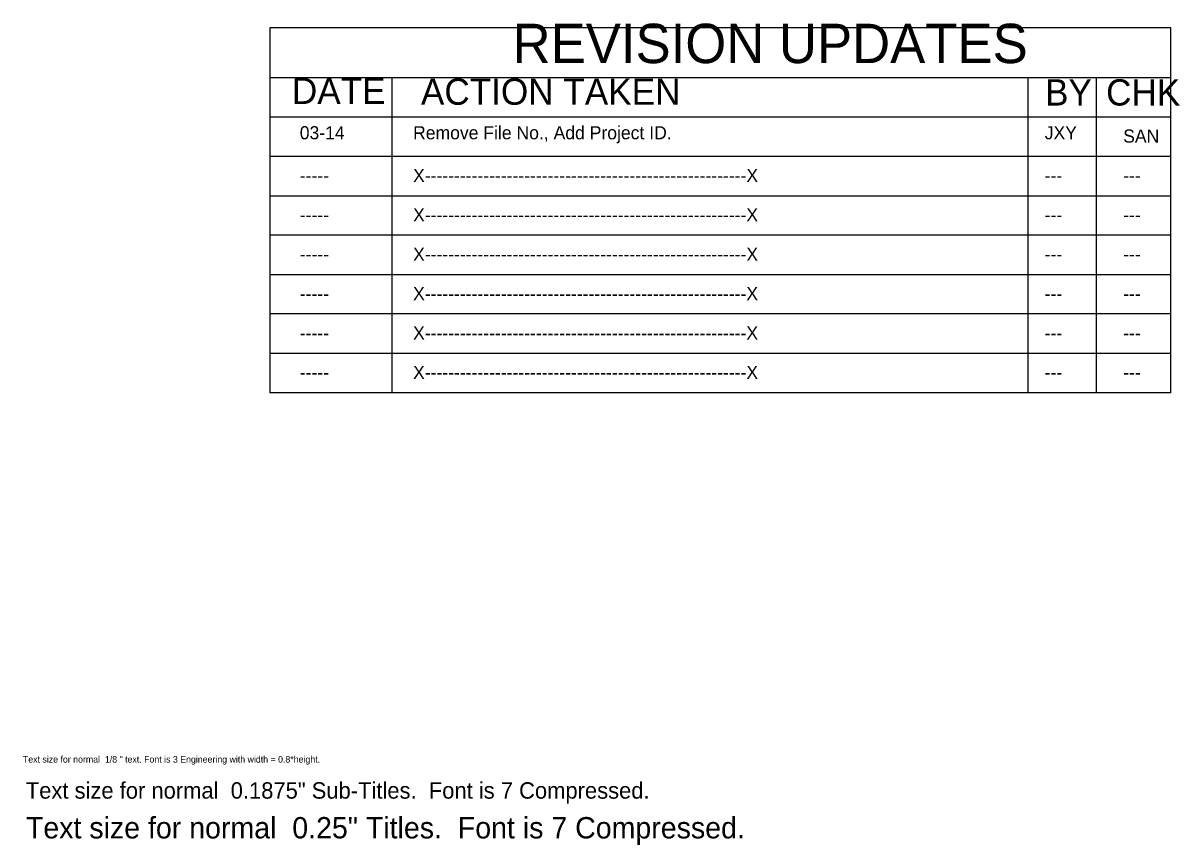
# Model space of a CAD drawing. Extents: x -0.04 to 4.87, y 0 to 1.83.
# Drawn here: x 3.035 to 4.87, y 0.217 to 1.521 of the extents above; entities that cross this region are included whole.
import ezdxf

# ---------------------------------------------------------------- set-up
doc = ezdxf.new("R2010")
doc.units = 0
doc.layers.add('BR_BORDER LINES', color=7, linetype='Continuous')
doc.layers.add('BR_TEXT', color=7, linetype='Continuous')

msp = doc.modelspace()

# ---------------------------------------------------------------- linework, layer by layer
at = {"layer": 'BR_BORDER LINES'}
for p, q in [((4.8558, 1.5135), (3.4261, 1.5135)), ((3.4261, 1.5135), (3.4261, 0.9345)), ((4.8558, 0.9345), (4.8558, 1.5135)), ((3.4261, 1.4346), (4.8558, 1.4346)), ((3.62, 1.4346), (3.62, 0.9345)), ((4.6296, 0.9345), (4.6296, 1.4346)), ((4.7373, 1.4346), (4.7373, 0.9345)), ((3.4261, 1.3721), (4.8558, 1.3721)), ((4.8558, 1.3095), (3.4261, 1.3095)), ((3.4261, 1.247), (4.8558, 1.247)), ((4.8558, 1.1845), (3.4261, 1.1845)), ((3.4261, 1.122), (4.8558, 1.122)), ((4.8558, 1.0595), (3.4261, 1.0595)), ((3.4261, 0.997), (4.8558, 0.997)), ((4.8558, 0.9345), (3.4261, 0.9345))]:
    msp.add_line(p, q, dxfattribs=at)

# ---------------------------------------------------------------- texts
at = {"layer": 'BR_TEXT'}
for s, height, p in [('REVISION UPDATES', 0.0625, (3.8114, 1.4575)), ('DATE', 0.04167, (3.4613, 1.3926)), ('ACTION TAKEN', 0.041667, (3.666, 1.3914)), ('BY', 0.04167, (4.6562, 1.3902)), ('CHK', 0.04167, (4.7531, 1.3902)), ('Remove File No., Add Project ID.                         ', 0.020833, (3.6535, 1.3366)), ('03-14', 0.02083, (3.4737, 1.3366)), ('JXY', 0.02083, (4.6557, 1.3366)), ('SAN', 0.02083, (4.7802, 1.3313)), ('X-------------------------------------------------------X', 0.020833, (3.6535, 1.2688)), ('-----', 0.02083, (3.4737, 1.2688)), ('---', 0.02083, (4.6557, 1.2688)), ('---', 0.02083, (4.7802, 1.2688)), ('-----', 0.02083, (3.4737, 1.2063)), ('X-------------------------------------------------------X', 0.020833, (3.6535, 1.2063)), ('---', 0.02083, (4.6557, 1.2063)), ('---', 0.02083, (4.7802, 1.2063)), ('X-------------------------------------------------------X', 0.020833, (3.6535, 1.1438)), ('-----', 0.02083, (3.4737, 1.1438)), ('---', 0.02083, (4.6557, 1.1438)), ('---', 0.02083, (4.7802, 1.1438)), ('X-------------------------------------------------------X', 0.020833, (3.6535, 1.0813)), ('-----', 0.02083, (3.4737, 1.0813)), ('---', 0.02083, (4.6557, 1.0813)), ('---', 0.02083, (4.7802, 1.0813)), ('-----', 0.02083, (3.4737, 1.0188)), ('X-------------------------------------------------------X', 0.020833, (3.6535, 1.0188)), ('---', 0.02083, (4.6557, 1.0188)), ('---', 0.02083, (4.7802, 1.0188)), ('X-------------------------------------------------------X', 0.020833, (3.6535, 0.9563)), ('-----', 0.02083, (3.4737, 0.9563)), ('---', 0.02083, (4.6557, 0.9563)), ('---', 0.02083, (4.7802, 0.9563)), (' Text size for normal  1/8 " text. Font is 3 Engineering with width = 0.8*height.', 0.010417, (3.0306, 0.3475)), ('Text size for normal  0.1875" Sub-Titles.  Font is 7 Compressed.', 0.026042, (3.039, 0.2903)), ('Text size for normal  0.25" Titles.  Font is 7 Compressed.', 0.033854, (3.0392, 0.2272))]:
    msp.add_text(s, height=height, dxfattribs=at).set_placement(p)

doc.saveas('drawing.dxf')
